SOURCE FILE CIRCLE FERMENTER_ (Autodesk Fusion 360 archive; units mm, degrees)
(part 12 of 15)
work_plane "Piano di lavoro1" AlongDistance -5
sketch "Schizzo2" plane through (-5, 0, 0) normal (1, 0, 0) x axis (0, 1, 0)
  line L1 (-88.4, 164.9) -> (-88.4, 163.1)
  curve K1 (-88.3168, 169.8415) -> (-88.4, 164.9)
  curve K2 (-81.9366, 174.4086) -> (-88.3168, 169.8415)
  curve K3 (-69.9527, 188.2187) -> (-74.509, 181.8379)
  curve K4 (-65, 188.3) -> (-69.9527, 188.2187)
  line L2 (-10.9836, 188.3) -> (-65, 188.3)
  line L3 (65, 188.3) -> (10.9836, 188.3)
  curve K5 (65, 188.3) -> (69.9527, 188.2187)
  curve K6 (69.9527, 188.2187) -> (74.509, 181.8379)
  curve K7 (81.9366, 174.4086) -> (88.3168, 169.8415)
  curve K8 (88.3168, 169.8415) -> (88.4, 164.9)
  line L4 (88.4, 163.1) -> (88.4, 164.9)
  line L5 (86.4, 157.1) -> (86.4, 163.1)
  line L6 (88.2, 157.1) -> (86.4, 157.1)
  line L7 (88.2, 159.9) -> (88.2, 157.1)
  line L8 (90, 159.9) -> (88.2, 159.9)
  line L9 (90, 164.9) -> (90, 159.9)
  curve K9 (90, 164.9) -> (65, 189.9)
  line L10 (-65, 189.9) -> (65, 189.9)
  curve K10 (-90, 164.9) -> (-65, 189.9)
  line L11 (-90, 159.9) -> (-90, 164.9)
  line L12 (-88.2, 159.9) -> (-90, 159.9)
  line L13 (-88.2, 157.1) -> (-88.2, 159.9)
  line L14 (-86.4, 157.1) -> (-88.2, 157.1)
  line L15 (-86.4, 163.1) -> (-86.4, 157.1)
  line L16 (86.4, 163.1) -> (88.4, 163.1)
  line L17 (-88.4, 163.1) -> (-86.4, 163.1)
  circle C1 centre (80.2735, 180.1735) radius 1.75
  circle C2 centre (0, 183.9) radius 1.75
  circle C3 centre (-80.2735, 180.1735) radius 1.75
  arc A1 centre (-80.2735, 180.1735) radius 6 clockwise from (-74.509, 181.8379) to (-81.9366, 174.4086)
  arc A2 centre (-10.9836, 183.3) radius 5 clockwise from (-10.9836, 188.3) to (-5.9911, 183.5727)
  arc A3 centre (0, 183.9) radius 6 clockwise from (5.9911, 183.5727) to (-5.9911, 183.5727)
  arc A4 centre (10.9836, 183.3) radius 5 clockwise from (5.9911, 183.5727) to (10.9836, 188.3)
  arc A5 centre (80.2735, 180.1735) radius 6 clockwise from (81.9366, 174.4086) to (74.509, 181.8379)
  circle C4 centre (80.2735, 180.1735) radius 3
  circle C5 centre (0, 183.9) radius 3
  circle C6 centre (-80.2735, 180.1735) radius 3
  concentric C1 C4
  concentric C2 C5
  concentric C3 C6
  dimension "d1698" diameter C4 = 6
  dimension "d1699" diameter C5 = 6
  dimension "d1700" diameter C6 = 6
extrude "Estrusione3" cut sketch "Schizzo2" profile of C1 C2 C3 C4 C5 C6 against normal blind 17.158
fillet "Raccordo1" radius 1
component_from_bodies "Corpo->Comp2"
mirror "Specchio1" mirrorStitchTolerance 0.1
sketch "Schizzo1" plane through (0, 0, 0) normal (1, 0, 0) x axis (0, 1, 0)
  line L1 (54, 115) -> (-54, 115)
  line L2 (54, 116.8) -> (54, 115)
  curve K1 (64.9968, 129.9) -> (54, 116.8)
  line L3 (65, 129.9) -> (64.9968, 129.9)
  curve K2 (90, 154.9) -> (65, 129.9)
  line L4 (90, 159.9) -> (90, 154.9)
  line L5 (88.4, 159.9) -> (90, 159.9)
  line L6 (88.4, 154.9) -> (88.4, 159.9)
  curve K3 (88.3168, 149.9585) -> (88.4, 154.9)
  curve K4 (88.3168, 149.9585) -> (81.9366, 145.3914)
  curve K5 (74.509, 137.9621) -> (69.9527, 131.5813)
  curve K6 (65, 131.5) -> (69.9527, 131.5813)
  line L7 (64.418, 131.5) -> (65, 131.5)
  curve K7 (64.418, 131.5) -> (62.9273, 130.1669)
  curve K8 (62.9273, 130.1669) -> (62.64, 129.4383)
  curve K9 (62.64, 129.4383) -> (52, 116.8)
  line L8 (52, 116.6) -> (52, 116.8)
  line L9 (-52, 116.6) -> (52, 116.6)
  line L10 (-52, 116.8) -> (-52, 116.6)
  curve K10 (-62.64, 129.4383) -> (-52, 116.8)
  curve K11 (-62.9273, 130.1669) -> (-62.64, 129.4383)
  curve K12 (-64.418, 131.5) -> (-62.9273, 130.1669)
  line L11 (-65, 131.5) -> (-64.418, 131.5)
  curve K13 (-65, 131.5) -> (-69.9527, 131.5813)
  curve K14 (-74.509, 137.9621) -> (-69.9527, 131.5813)
  curve K15 (-88.3168, 149.9585) -> (-81.9366, 145.3914)
  curve K16 (-88.3168, 149.9585) -> (-88.4, 154.9)
  line L12 (-88.4, 159.9) -> (-88.4, 154.9)
  line L13 (-90, 159.9) -> (-88.4, 159.9)
  line L14 (-90, 154.9) -> (-90, 159.9)
  curve K17 (-90, 154.9) -> (-65, 129.9)
  line L15 (-64.9968, 129.9) -> (-65, 129.9)
  curve K18 (-64.9968, 129.9) -> (-54, 116.8)
  line L16 (-54, 115) -> (-54, 116.8)
  circle C1 centre (80.2735, 139.6265) radius 2
  circle C2 centre (-80.2735, 139.6265) radius 2
  arc A1 centre (80.2735, 139.6265) radius 6 clockwise from (74.509, 137.9621) to (81.9366, 145.3914)
  arc A2 centre (-80.2735, 139.6265) radius 6 clockwise from (-81.9366, 145.3914) to (-74.509, 137.9621)
extrude "Estrusione1" add sketch "Schizzo1" profile of C1 C2 against normal blind 4
sketch "Schizzo2" plane through (0, 0, 0) normal (1, 0, 0) x axis (0, 1, 0)
  circle C1 centre (-80.2735, 139.6265) radius 1.75
  circle C2 centre (80.2735, 139.6265) radius 1.75
  circle C3 centre (-80.2735, 139.6265) radius 2
  circle C4 centre (80.2735, 139.6265) radius 2
  dimension "d1709" diameter C1 = 3.5
  dimension "d1710" diameter C2 = 3.5
extrude "Estrusione2" cut sketch "Schizzo2" profile of C1 C2 against normal blind 32.997
work_plane "Piano di lavoro1" AlongDistance -6
sketch "Schizzo3" plane through (-6, 0, 0) normal (1, 0, 0) x axis (0, 1, 0)
  circle C1 centre (-80.2735, 139.6265) radius 1.75
  circle C2 centre (80.2735, 139.6265) radius 1.75
  circle C3 centre (80.2735, 139.6265) radius 3
  circle C4 centre (-80.2735, 139.6265) radius 3
  concentric C2 C3
  concentric C1 C4
  dimension "d1714" diameter C3 = 6
  dimension "d1715" diameter C4 = 6
extrude "Estrusione3" cut sketch "Schizzo3" against normal blind 15
fillet "Raccordo2" radius 2
sketch "Schizzo1" plane through (-160, 0, 0) normal (-1, 0, 0) x axis (0, -1, 0)
  line L1 (-65, 189.9) -> (65, 189.9)
  curve K1 (-90, 164.9) -> (-65, 189.9)
  line L2 (-90, 159.9) -> (-90, 164.9)
  line L3 (-85.9, 159.9) -> (-90, 159.9)
  curve K2 (-83.203, 163.6818) -> (-81.8715, 165.8329)
  curve K3 (-81.897, 166.2391) -> (-81.8715, 165.8329)
  curve K4 (-81.897, 166.2391) -> (-65, 181.8)
  line L4 (-6.3246, 181.8) -> (-65, 181.8)
  curve K5 (-5.9329, 181.7743) -> (-6.3246, 181.8)
  curve K6 (-5.9329, 181.7743) -> (-3.7812, 183.1048)
  curve K7 (5.9329, 181.7743) -> (3.7812, 183.1048)
  curve K8 (5.9329, 181.7743) -> (6.3246, 181.8)
  line L5 (65, 181.8) -> (6.3246, 181.8)
  curve K9 (81.897, 166.2391) -> (65, 181.8)
  curve K10 (81.897, 166.2391) -> (81.8715, 165.8329)
  curve K11 (83.203, 163.6818) -> (81.8715, 165.8329)
  line L6 (90, 159.9) -> (85.9, 159.9)
  line L7 (90, 164.9) -> (90, 159.9)
  curve K12 (90, 164.9) -> (65, 189.9)
  curve K13 (-3.614, 139.7143) -> (-6.3246, 138)
  line L8 (-65, 138) -> (-6.3246, 138)
  curve K14 (-81.897, 153.5609) -> (-65, 138)
  curve K15 (-81.897, 153.5609) -> (-80.184, 156.2868)
  line L9 (-90, 159.9) -> (-85.9, 159.9)
  line L10 (-90, 154.9) -> (-90, 159.9)
  curve K16 (-90, 154.9) -> (-65, 129.9)
  line L11 (65, 129.9) -> (-65, 129.9)
  curve K17 (90, 154.9) -> (65, 129.9)
  line L12 (90, 159.9) -> (90, 154.9)
  line L13 (85.9, 159.9) -> (90, 159.9)
  curve K18 (81.897, 153.5609) -> (80.184, 156.2868)
  curve K19 (81.897, 153.5609) -> (65, 138)
  line L14 (6.3246, 138) -> (65, 138)
  curve K20 (3.614, 139.7143) -> (6.3246, 138)
  line L15 (-88, 154.9) -> (-88, 159.9)
  curve K21 (-88, 154.9) -> (-65, 131.9)
  line L16 (65, 131.9) -> (-65, 131.9)
  curve K22 (88, 154.9) -> (65, 131.9)
  line L17 (88, 159.9) -> (88, 154.9)
  line L18 (88, 164.9) -> (88, 159.9)
  curve K23 (88, 164.9) -> (65, 187.9)
  line L19 (-65, 187.9) -> (65, 187.9)
  curve K24 (-88, 164.9) -> (-65, 187.9)
  line L20 (-88, 159.9) -> (-88, 164.9)
  arc A1 centre (-81.9, 159.9) radius 4 clockwise from (-85.9, 159.9) to (-83.203, 163.6818)
  arc A2 centre (0, 181.8) radius 4 clockwise from (-3.7812, 183.1048) to (3.7812, 183.1048)
  arc A3 centre (81.9, 159.9) radius 4 clockwise from (83.203, 163.6818) to (85.9, 159.9)
  arc A4 centre (0, 138) radius 4 clockwise from (-3.614, 139.7143) to (3.614, 139.7143)
  arc A5 centre (-81.9, 159.9) radius 4 clockwise from (-85.9, 159.9) to (-80.184, 156.2868)
  arc A6 centre (81.9, 159.9) radius 4 clockwise from (80.184, 156.2868) to (85.9, 159.9)
  circle C1 centre (-81.9, 159.9) radius 1.75
  circle C2 centre (0, 138) radius 1.75
  circle C3 centre (81.9, 159.9) radius 1.75
  dimension "d1724" = -2
extrude "Estrusione1" new body sketch "Schizzo1" profile of L3 A1 K2 K3 K4 L4 K5 K6 A2 K7 K8 L5 K9 K10 K11 A3 L6 A4 K13 L8 K14 K15 A5 L9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 along normal blind 3
sketch "Schizzo9" plane through (160, 0, 0) normal (-1, 0, 0) x axis (0, -1, 0)
  line L1 (14.45, 176.75) -> (14.45, 143.05)
  line L2 (74.85, 177.75) -> (15.45, 177.75)
  line L3 (75.85, 143.05) -> (75.85, 176.75)
  line L4 (15.45, 142.05) -> (74.85, 142.05)
  line L5 (9.65, 140) -> (9.65, 179.8)
  line L6 (3.873, 138) -> (7.65, 138)
  line L7 (-65, 138) -> (-3.873, 138)
  curve K1 (-76.9033, 139.6916) -> (-65, 138)
  curve K2 (-79.0124, 141.3132) -> (-76.9033, 139.6916)
  curve K3 (-81.9, 154.9) -> (-79.0124, 141.3132)
  line L8 (-81.9, 156.027) -> (-81.9, 154.9)
  line L9 (-81.9, 164.9) -> (-81.9, 163.773)
  curve K4 (-79.0124, 178.4868) -> (-81.9, 164.9)
  curve K5 (-76.9033, 180.1084) -> (-79.0124, 178.4868)
  curve K6 (-65, 181.8) -> (-76.9033, 180.1084)
  line L10 (-3.873, 181.8) -> (-65, 181.8)
  line L11 (7.65, 181.8) -> (3.873, 181.8)
  curve K7 (74.4055, 134.6069) -> (65, 134)
  curve K8 (81.0094, 137.6898) -> (74.4055, 134.6069)
  curve K9 (85.9, 154.9) -> (81.0094, 137.6898)
  line L12 (85.9, 164.9) -> (85.9, 154.9)
  curve K10 (81.0094, 182.1102) -> (85.9, 164.9)
  curve K11 (74.4056, 185.1931) -> (81.0094, 182.1102)
  curve K12 (65, 185.8) -> (74.4056, 185.1931)
  line L13 (-65, 185.8) -> (65, 185.8)
  curve K13 (-78.818, 183.6203) -> (-65, 185.8)
  curve K14 (-81.9485, 181.2032) -> (-78.818, 183.6203)
  curve K15 (-85.9, 164.9) -> (-81.9485, 181.2032)
  line L14 (-85.9, 154.9) -> (-85.9, 164.9)
  curve K16 (-81.9485, 138.5968) -> (-85.9, 154.9)
  curve K17 (-78.818, 136.1797) -> (-81.9485, 138.5968)
  curve K18 (-65, 134) -> (-78.818, 136.1797)
  line L15 (65, 134) -> (-65, 134)
  line L16 (-35.35, 159.9) -> (9.65, 159.9)
  line L17 (9.65, 159.9) -> (-35.35, 159.9)
  line L18 (9.65, 165.9) -> (9.65, 159.9)
  line L19 (-35.35, 165.9) -> (9.65, 165.9)
  line L20 (-35.35, 159.9) -> (-35.35, 165.9)
  line L21 (-35.35, 153.9) -> (9.65, 153.9)
  line L22 (-35.35, 159.9) -> (-35.35, 153.9)
  arc A1 centre (15.45, 176.75) radius 1 clockwise from (14.45, 176.75) to (15.45, 177.75)
  arc A2 centre (74.85, 176.75) radius 1 clockwise from (74.85, 177.75) to (75.85, 176.75)
  arc A3 centre (74.85, 143.05) radius 1 clockwise from (75.85, 143.05) to (74.85, 142.05)
  arc A4 centre (15.45, 143.05) radius 1 clockwise from (15.45, 142.05) to (14.45, 143.05)
  arc A5 centre (7.65, 140) radius 2 clockwise from (9.65, 140) to (7.65, 138)
  arc A6 centre (3.873, 139) radius 1 clockwise from (3.873, 138) to (2.9047, 138.75)
  arc A7 centre (0, 138) radius 3 clockwise from (-2.9047, 138.75) to (2.9047, 138.75)
  arc A8 centre (-3.873, 139) radius 1 clockwise from (-2.9047, 138.75) to (-3.873, 138)
  arc A9 centre (-80.9, 156.027) radius 1 clockwise from (-81.9, 156.027) to (-81.15, 156.9953)
  arc A10 centre (-81.9, 159.9) radius 3 clockwise from (-81.15, 162.8047) to (-81.15, 156.9953)
  arc A11 centre (-80.9, 163.773) radius 1 clockwise from (-81.15, 162.8047) to (-81.9, 163.773)
  arc A12 centre (-3.873, 180.8) radius 1 clockwise from (-3.873, 181.8) to (-2.9047, 181.05)
  arc A13 centre (0, 181.8) radius 3 clockwise from (2.9047, 181.05) to (-2.9047, 181.05)
  arc A14 centre (3.873, 180.8) radius 1 clockwise from (2.9047, 181.05) to (3.873, 181.8)
  arc A15 centre (7.65, 179.8) radius 2 clockwise from (7.65, 181.8) to (9.65, 179.8)
  circle C1 centre (-81.9, 159.9) radius 1.75
  circle C2 centre (81.9, 159.9) radius 1.75
  circle C3 centre (0, 138) radius 1.75
  circle C4 centre (0, 181.8) radius 1.75
  point P66 (9.65, 159.9)
  point P69 (9.65, 165.9)
  point P67 (-35.35, 159.9)
  point P73 (-35.35, 159.9)
  point P71 (9.65, 153.9)
  point P70 (-35.35, 165.9)
  point P72 (-35.35, 153.9)
  midpoint L5 P66
  perpendicular L5 L16
  horizontal L17
  vertical L18
  horizontal L19
  vertical L20
  coincident L5 P69
  symmetric P67 L16 P73
  symmetric L16 P69 P71
  symmetric L16 P70 P72
  dimension "d1727" distance L5 P67 = 45
  dimension "d1728" distance P67 P70 = 6
extrude "Estrusione7" new body sketch "Schizzo9" profile of L5 L17 L18 L19 L20 L21 L22 to an object
combine "Combina4"
sketch "Schizzo10" plane through (170, 0, 0) normal (1, 0, 0) x axis (0, 1, 0)
  curve K1 (-71.9729, 151.8273) -> (-72, 154.9)
  line L1 (-72, 164.9) -> (-72, 154.9)
  curve K2 (-72, 164.9) -> (-71.9729, 167.9727)
  curve K3 (-71.9729, 167.9727) -> (-68.0604, 171.8773)
  curve K4 (-68.0604, 171.8773) -> (-65, 171.9)
  line L2 (-30, 171.9) -> (-65, 171.9)
  curve K5 (-30, 171.9) -> (-26.9396, 171.8773)
  curve K6 (-26.9396, 171.8773) -> (-23.0271, 167.9727)
  curve K7 (-23.0271, 167.9727) -> (-23, 164.9)
  line L3 (-23, 154.9) -> (-23, 164.9)
  curve K8 (-23, 154.9) -> (-23.0271, 151.8273)
  curve K9 (-23.0271, 151.8273) -> (-26.9396, 147.9227)
  curve K10 (-26.9396, 147.9227) -> (-30, 147.9)
  line L4 (-65, 147.9) -> (-30, 147.9)
  curve K11 (-65, 147.9) -> (-68.0604, 147.9227)
  curve K12 (-68.0604, 147.9227) -> (-71.9729, 151.8273)
  line L5 (-85.9, 154.9) -> (-85.9, 164.9)
  curve K13 (-65, 134) -> (-85.9, 154.9)
  line L6 (65, 134) -> (-65, 134)
  curve K14 (85.9, 154.9) -> (65, 134)
  line L7 (85.9, 164.9) -> (85.9, 154.9)
  curve K15 (85.9, 164.9) -> (65, 185.8)
  line L8 (-65, 185.8) -> (65, 185.8)
  curve K16 (-65, 185.8) -> (-85.9, 164.9)
  circle C1 centre (-5.2385, 159.9) radius 2.5
  circle C2 centre (9.7615, 159.9) radius 2.5
  circle C3 centre (24.7615, 159.9) radius 2.5
  circle C4 centre (60, 159.9) radius 3.5
  circle C5 centre (81.9, 159.9) radius 1.75
  circle C6 centre (0, 181.8) radius 1.75
  circle C7 centre (0, 138) radius 1.75
  circle C8 centre (-81.9, 159.9) radius 1.75
extrude "Estrusione1" cut sketch "Schizzo10" profile of C1 C2 C3 against normal blind 25.97
fillet "Raccordo3" radius 8 6
sketch "Schizzo8" plane through (170, 0, 0) normal (1, 0, 0) x axis (0, 1, 0)
  curve K1 (-71.9729, 151.8273) -> (-72, 154.9)
  line L1 (-72, 164.9) -> (-72, 154.9)
  curve K2 (-72, 164.9) -> (-71.9729, 167.9727)
  curve K3 (-71.9729, 167.9727) -> (-68.0604, 171.8773)
  curve K4 (-68.0604, 171.8773) -> (-65, 171.9)
  line L2 (-30, 171.9) -> (-65, 171.9)
  curve K5 (-30, 171.9) -> (-26.9396, 171.8773)
  curve K6 (-26.9396, 171.8773) -> (-23.0271, 167.9727)
  curve K7 (-23.0271, 167.9727) -> (-23, 164.9)
  line L3 (-23, 154.9) -> (-23, 164.9)
  curve K8 (-23, 154.9) -> (-23.0271, 151.8273)
  curve K9 (-23.0271, 151.8273) -> (-26.9396, 147.9227)
  curve K10 (-26.9396, 147.9227) -> (-30, 147.9)
  line L4 (-65, 147.9) -> (-30, 147.9)
  curve K11 (-65, 147.9) -> (-68.0604, 147.9227)
  curve K12 (-68.0604, 147.9227) -> (-71.9729, 151.8273)
  line L5 (-85.9, 154.9) -> (-85.9, 164.9)
  curve K13 (-65, 134) -> (-85.9, 154.9)
  line L6 (65, 134) -> (-65, 134)
  curve K14 (85.9, 154.9) -> (65, 134)
  line L7 (85.9, 164.9) -> (85.9, 154.9)
  curve K15 (85.9, 164.9) -> (65, 185.8)
  line L8 (-65, 185.8) -> (65, 185.8)
  curve K16 (-65, 185.8) -> (-85.9, 164.9)
  circle C1 centre (-5.2385, 159.9) radius 2.5
  circle C2 centre (9.7615, 159.9) radius 2.5
  circle C3 centre (24.7615, 159.9) radius 2.5
  circle C4 centre (60, 159.9) radius 3.5
  circle C5 centre (81.9, 159.9) radius 1.75
  circle C6 centre (0, 181.8) radius 1.75
  circle C7 centre (0, 138) radius 1.75
  circle C8 centre (-81.9, 159.9) radius 1.75
extrude "Estrusione5" add sketch "Schizzo8" profile of C1 C2 C3 against normal blind 3
component_from_bodies "Corpo->Comp1"
component_from_bodies "Corpo->Comp2"
component_from_bodies "Corpo->Comp1"
component_from_bodies "Corpo->Comp2"
component_from_bodies "Corpo->Comp1"
component_from_bodies "Corpo->Comp2"
sketch "Schizzo9" plane through (-160, 0, 0) normal (1, 0, 0) x axis (0, 1, 0)
  line L1 (-65, 187.9) -> (65, 187.9)
  curve K1 (-88, 164.9) -> (-65, 187.9)
  line L2 (-88, 154.9) -> (-88, 164.9)
  curve K2 (-88, 154.9) -> (-65, 131.9)
  line L3 (65, 131.9) -> (-65, 131.9)
  curve K3 (88, 154.9) -> (65, 131.9)
  line L4 (88, 164.9) -> (88, 154.9)
  curve K4 (88, 164.9) -> (65, 187.9)
  circle C1 centre (81.9, 159.9) radius 1.75
  circle C2 centre (-81.9, 159.9) radius 1.75
  circle C3 centre (0, 138) radius 1.75
sketch "Schizzo10" plane through (170, 0, 0) normal (1, 0, 0) x axis (0, 1, 0)
  curve K1 (-71.9729, 151.8273) -> (-72, 154.9)
  line L1 (-72, 164.9) -> (-72, 154.9)
  curve K2 (-72, 164.9) -> (-71.9729, 167.9727)
  curve K3 (-71.9729, 167.9727) -> (-68.0604, 171.8773)
  curve K4 (-68.0604, 171.8773) -> (-65, 171.9)
  line L2 (-30, 171.9) -> (-65, 171.9)
  curve K5 (-30, 171.9) -> (-26.9396, 171.8773)
  curve K6 (-26.9396, 171.8773) -> (-23.0271, 167.9727)
  curve K7 (-23.0271, 167.9727) -> (-23, 164.9)
  line L3 (-23, 154.9) -> (-23, 164.9)
  curve K8 (-23, 154.9) -> (-23.0271, 151.8273)
  curve K9 (-23.0271, 151.8273) -> (-26.9396, 147.9227)
  curve K10 (-26.9396, 147.9227) -> (-30, 147.9)
  line L4 (-65, 147.9) -> (-30, 147.9)
  curve K11 (-65, 147.9) -> (-68.0604, 147.9227)
  curve K12 (-68.0604, 147.9227) -> (-71.9729, 151.8273)
  line L5 (-85.9, 154.9) -> (-85.9, 164.9)
  curve K13 (-65, 134) -> (-85.9, 154.9)
  line L6 (65, 134) -> (-65, 134)
  curve K14 (85.9, 154.9) -> (65, 134)
  line L7 (85.9, 164.9) -> (85.9, 154.9)
  curve K15 (85.9, 164.9) -> (65, 185.8)
  line L8 (-65, 185.8) -> (65, 185.8)
  curve K16 (-65, 185.8) -> (-85.9, 164.9)
  circle C1 centre (60, 159.9) radius 3.5
  circle C2 centre (81.9, 159.9) radius 1.75
  circle C3 centre (0, 181.8) radius 1.75
  circle C4 centre (0, 138) radius 1.75
  circle C5 centre (-81.9, 159.9) radius 1.75
copy_paste "TagliaIncolla1"
sketch "Schizzo11" plane through (158, 0, 0) normal (1, 0, 0) x axis (0, 1, 0)
  line L1 (-86.7, -206.7) -> (-86.7, -127.1)
  line L2 (-82.7, -206.7) -> (-86.7, -206.7)
  curve K1 (-64.8, -224.6) -> (-82.7, -206.7)
  line L3 (-64.8, -228.6) -> (-64.8, -224.6)
  line L4 (64.8, -228.6) -> (-64.8, -228.6)
  line L5 (64.8, -224.6) -> (64.8, -228.6)
  curve K2 (82.7, -206.7) -> (64.8, -224.6)
  line L6 (86.7, -206.7) -> (82.7, -206.7)
  line L7 (86.7, -127.1) -> (86.7, -206.7)
  line L8 (82.7, -127.1) -> (86.7, -127.1)
  curve K3 (64.8, -109.2) -> (82.7, -127.1)
  line L9 (64.8, -105.2) -> (64.8, -109.2)
  line L10 (-64.8, -105.2) -> (64.8, -105.2)
  line L11 (-64.8, -109.2) -> (-64.8, -105.2)
  curve K4 (-82.7, -127.1) -> (-64.8, -109.2)
  line L12 (-86.7, -127.1) -> (-82.7, -127.1)
  circle C1 centre (-45, -110.3265) radius 1.75
  circle C2 centre (45, -110.3265) radius 1.75
  circle C3 centre (-81.5735, -166.9) radius 1.75
  circle C4 centre (81.5735, -166.9) radius 1.75
  circle C5 centre (45, -223.4735) radius 1.75
  circle C6 centre (-45, -223.4735) radius 1.75
sketch "Schizzo12" plane through (0, 0, -227.3) normal (0, 0, 1) x axis (-1, 0, 0)
  line L1 (-95, 64.5) -> (95, 64.5)
  curve K1 (-134.5, 25) -> (-95, 64.5)
  line L2 (-134.5, -25) -> (-134.5, 25)
  curve K2 (-134.5, -25) -> (-95, -64.5)
  line L3 (95, -64.5) -> (-95, -64.5)
  curve K3 (134.5, -25) -> (95, -64.5)
  line L4 (134.5, 25) -> (134.5, -25)
  curve K4 (134.5, 25) -> (95, 64.5)
  circle C1 centre (47.5, 60) radius 1.75
  circle C2 centre (130, 25) radius 1.75
  circle C3 centre (95, -60) radius 1.75
  circle C4 centre (130, -25) radius 1.75
  circle C5 centre (-47.5, -60) radius 1.75
  circle C6 centre (-130, -25) radius 1.75
  circle C7 centre (-130, 25) radius 1.75
  circle C8 centre (-47.5, 60) radius 1.75
sketch "Schizzo13" plane through (0, 85.4, 0) normal (0, -1, 0) x axis (1, 0, 0)
  curve K1 (95, -127.4) -> (134.5, -166.9)
  line L1 (-95, -127.4) -> (95, -127.4)
  curve K2 (-95, -127.4) -> (-134.5, -166.9)
  curve K3 (-134.5, -166.9) -> (-95, -206.4)
  line L2 (95, -206.4) -> (-95, -206.4)
  curve K4 (134.5, -166.9) -> (95, -206.4)
  circle C1 centre (-130, -166.9) radius 1.75
  circle C2 centre (130, -166.9) radius 1.75
  circle C3 centre (47.5, -131.9) radius 1.75
  circle C4 centre (-47.5, -131.9) radius 1.75
  circle C5 centre (47.5, -201.9) radius 1.75
  circle C6 centre (-47.5, -201.9) radius 1.75
sketch "Schizzo14" plane through (0, -75.4, 0) normal (0, -1, 0) x axis (1, 0, 0)
  line L1 (142, -159.4) -> (-142, -159.4)
  curve K1 (143, -158.4) -> (142, -159.4)
  line L2 (143, -144.4) -> (143, -158.4)
  curve K2 (142, -143.4) -> (143, -144.4)
  line L3 (-142, -143.4) -> (142, -143.4)
  curve K3 (-142, -143.4) -> (-143, -144.4)
  line L4 (-143, -158.4) -> (-143, -144.4)
  curve K4 (-143, -158.4) -> (-142, -159.4)
  circle C1 centre (-139, -147.4) radius 1.75
  circle C2 centre (-139, -155.4) radius 1.75
  circle C3 centre (139, -155.4) radius 1.75
  circle C4 centre (139, -147.4) radius 1.75
remove_instance "RimuoviIstanza1"
sketch "Schizzo15" plane through (-183, 0, 0) normal (-1, 0, 0) x axis (0, -1, 0)
  line L1 (39.4, -144) -> (-39.4, -144)
  line L2 (45.9, -183.3) -> (45.9, -150.5)
  line L3 (-39.4, -189.8) -> (39.4, -189.8)
  line L4 (-45.9, -150.5) -> (-45.9, -183.3)
  line L5 (-86.5355, -176.1047) -> (-79.4522, -169.0213)
  line L6 (-88, -206.9) -> (-88, -179.6402)
  curve K1 (-88, -206.9) -> (-65, -229.9)
  line L7 (65, -229.9) -> (-65, -229.9)
  curve K2 (88, -206.9) -> (65, -229.9)
  line L8 (88, -179.6402) -> (88, -206.9)
  line L9 (79.4522, -169.0213) -> (86.5355, -176.1047)
  line L10 (86.5355, -157.6954) -> (79.4522, -164.7787)
  line L11 (88, -126.9) -> (88, -154.1598)
  curve K3 (88, -126.9) -> (65, -103.9)
  line L12 (-65, -103.9) -> (65, -103.9)
  curve K4 (-88, -126.9) -> (-65, -103.9)
  line L13 (-88, -154.1598) -> (-88, -126.9)
  line L14 (-79.4522, -164.7787) -> (-86.5355, -157.6954)
  arc A1 centre (39.4, -150.5) radius 6.5 clockwise from (39.4, -144) to (45.9, -150.5)
  arc A2 centre (39.4, -183.3) radius 6.5 clockwise from (45.9, -183.3) to (39.4, -189.8)
  arc A3 centre (-39.4, -183.3) radius 6.5 clockwise from (-39.4, -189.8) to (-45.9, -183.3)
  arc A4 centre (-39.4, -150.5) radius 6.5 clockwise from (-45.9, -150.5) to (-39.4, -144)
  circle C1 centre (-25, -107.5) radius 1.75
  circle C2 centre (25, -107.5) radius 1.75
  arc A5 centre (-81.5735, -166.9) radius 3 clockwise from (-79.4522, -164.7787) to (-79.4522, -169.0213)
  arc A6 centre (-83, -179.6402) radius 5 clockwise from (-88, -179.6402) to (-86.5355, -176.1047)
  arc A7 centre (83, -179.6402) radius 5 clockwise from (86.5355, -176.1047) to (88, -179.6402)
  arc A8 centre (81.5735, -166.9) radius 3 clockwise from (79.4522, -169.0213) to (79.4522, -164.7787)
  arc A9 centre (83, -154.1598) radius 5 clockwise from (88, -154.1598) to (86.5355, -157.6954)
  arc A10 centre (-83, -154.1598) radius 5 clockwise from (-86.5355, -157.6954) to (-88, -154.1598)
  circle C3 centre (25, -226.3) radius 1.75
  circle C4 centre (-25, -226.3) radius 1.75
sketch "Schizzo16" plane through (-150.8, 0, 0) normal (1, 0, 0) x axis (0, 1, 0)
  line L1 (-10.25, -207.2618) -> (10.25, -207.2618)
  line L2 (-10.25, -192.7618) -> (-10.25, -207.2618)
  line L3 (10.25, -192.7618) -> (-10.25, -192.7618)
  line L4 (10.25, -207.2618) -> (10.25, -192.7618)
  line L5 (83.1107, -126.9) -> (83.1107, -164.9033)
  curve K1 (65, -108.7893) -> (83.1107, -126.9)
  line L6 (-65, -108.7893) -> (65, -108.7893)
  curve K2 (-83.1107, -126.9) -> (-65, -108.7893)
  line L7 (-83.1107, -164.9033) -> (-83.1107, -126.9)
  line L8 (-83.1107, -206.9) -> (-83.1107, -168.8967)
  curve K3 (-65, -225.0107) -> (-83.1107, -206.9)
  line L9 (65, -225.0107) -> (-65, -225.0107)
  curve K4 (83.1107, -206.9) -> (65, -225.0107)
  line L10 (83.1107, -168.8967) -> (83.1107, -206.9)
  circle C1 centre (12.35, -200.0107) radius 1.55
  circle C2 centre (-39, -182.9) radius 1.875
  circle C3 centre (39, -182.9) radius 1.725
  circle C4 centre (-39, -150.9) radius 1.875
  circle C5 centre (39, -150.9) radius 1.725
  circle C6 centre (-21, -166.9) radius 12.5
  circle C7 centre (23, -166.9) radius 19.5
  circle C8 centre (0, -222.1) radius 1.75
  circle C9 centre (44.1, -111.7) radius 1.75
  arc A1 centre (82.6107, -168.8967) radius 0.5 clockwise from (82.3802, -168.453) to (83.1107, -168.8967)
  arc A2 centre (81.5735, -166.9) radius 1.75 clockwise from (82.3802, -168.453) to (82.3802, -165.347)
  arc A3 centre (82.6107, -164.9033) radius 0.5 clockwise from (83.1107, -164.9033) to (82.3802, -165.347)
  arc A4 centre (-82.6107, -164.9033) radius 0.5 clockwise from (-82.3802, -165.347) to (-83.1107, -164.9033)
  arc A5 centre (-81.5735, -166.9) radius 1.75 clockwise from (-82.3802, -165.347) to (-82.3802, -168.453)
  arc A6 centre (-82.6107, -168.8967) radius 0.5 clockwise from (-83.1107, -168.8967) to (-82.3802, -168.453)
  circle C10 centre (44.1, -222.1) radius 1.75
  circle C11 centre (-44.1, -222.1) radius 1.75
  circle C12 centre (-44.1, -111.7) radius 1.75
  circle C13 centre (0, -111.7) radius 1.75
sketch "Schizzo17" plane through (158, 0, 0) normal (1, 0, 0) x axis (0, 1, 0)
  line L1 (86.7, 91.3) -> (86.7, -63.3)
  line L2 (82.7, 91.3) -> (86.7, 91.3)
  curve K1 (64.8, 109.2) -> (82.7, 91.3)
  line L3 (64.8, 113.2) -> (64.8, 109.2)
  line L4 (-64.8, 113.2) -> (64.8, 113.2)
  line L5 (-64.8, 109.2) -> (-64.8, 113.2)
  curve K2 (-82.7, 91.3) -> (-64.8, 109.2)
  line L6 (-86.7, 91.3) -> (-82.7, 91.3)
  line L7 (-86.7, -63.3) -> (-86.7, 91.3)
  line L8 (-82.7, -63.3) -> (-86.7, -63.3)
  curve K3 (-64.8, -81.2) -> (-82.7, -63.3)
  line L9 (-64.8, -85.2) -> (-64.8, -81.2)
  line L10 (64.8, -85.2) -> (-64.8, -85.2)
  line L11 (64.8, -81.2) -> (64.8, -85.2)
  curve K4 (82.7, -63.3) -> (64.8, -81.2)
  line L12 (86.7, -63.3) -> (82.7, -63.3)
  circle C1 centre (81.5735, 14) radius 1.75
  circle C2 centre (-81.5735, 14) radius 1.75
  circle C3 centre (-81.5735, 71.5) radius 1.75
  circle C4 centre (-45, 108.0735) radius 1.75
  circle C5 centre (45, 108.0735) radius 1.75
  circle C6 centre (81.5735, 71.5) radius 1.75
  circle C7 centre (0, 108.0735) radius 1.75
  circle C8 centre (0, -80.0735) radius 1.75
  circle C9 centre (81.5735, -43.5) radius 1.75
  circle C10 centre (45, -80.0735) radius 1.75
  circle C11 centre (-45, -80.0735) radius 1.75
  circle C12 centre (-81.5735, -43.5) radius 1.75
sketch "Schizzo18" plane through (0, 0, -83.9) normal (0, 0, 1) x axis (-1, 0, 0)
  line L1 (-90, -28.4) -> (-26.2258, -28.4)
  curve K1 (-98.4, -20) -> (-90, -28.4)
  line L2 (-98.4, 20) -> (-98.4, -20)
  curve K2 (-90, 28.4) -> (-98.4, 20)
  line L3 (-26.2258, 28.4) -> (-90, 28.4)
  line L4 (74.1572, 16.6179) -> (-14.0208, 27.6401)
  line L5 (89.206, 6.8768) -> (81.4524, 13.4232)
  line L6 (81.4524, -13.4232) -> (89.206, -6.8768)
  line L7 (-14.0208, -27.6401) -> (74.1572, -16.6179)
  line L8 (-95, 64.5) -> (95, 64.5)
  curve K3 (-134.5, 25) -> (-95, 64.5)
  line L9 (-134.5, -25) -> (-134.5, 25)
  curve K4 (-134.5, -25) -> (-95, -64.5)
  line L10 (95, -64.5) -> (-95, -64.5)
  curve K5 (134.5, -25) -> (95, -64.5)
  line L11 (134.5, 25) -> (134.5, -25)
  curve K6 (134.5, 25) -> (95, 64.5)
  arc A1 centre (-26.2258, 70) radius 98.4 clockwise from (-14.0208, -27.6401) to (-26.2258, -28.4)
  arc A2 centre (-26.2258, -70) radius 98.4 clockwise from (-26.2258, 28.4) to (-14.0208, 27.6401)
  arc A3 centre (72.4207, 2.726) radius 14 clockwise from (74.1572, 16.6179) to (81.4524, 13.4232)
  arc A4 centre (83.4, 0) radius 9 clockwise from (89.206, 6.8768) to (89.206, -6.8768)
  arc A5 centre (72.4207, -2.726) radius 14 clockwise from (81.4524, -13.4232) to (74.1572, -16.6179)
  circle C1 centre (88, 16) radius 1.75
  circle C2 centre (-101.9, -16) radius 1.75
  circle C3 centre (88, -16) radius 1.75
  circle C4 centre (-101.9, 16) radius 1.75
  circle C5 centre (130, 25) radius 1.75
  circle C6 centre (95, 60) radius 1.75
  circle C7 centre (32, 60) radius 1.75
  circle C8 centre (32, -60) radius 1.75
  circle C9 centre (95, -60) radius 1.75
  circle C10 centre (130, -25) radius 1.75
  circle C11 centre (-130, -25) radius 1.75
  circle C12 centre (-95, -60) radius 1.75
  circle C13 centre (-32, -60) radius 1.75
  circle C14 centre (-32, 60) radius 1.75
  circle C15 centre (-95, 60) radius 1.75
  circle C16 centre (-130, 25) radius 1.75
sketch "Schizzo19" plane through (0, 0, 111.9) normal (0, 0, -1) x axis (1, 0, 0)
  line L1 (95, -64.5) -> (-95, -64.5)
  curve K1 (95, -64.5) -> (134.5, -25)
  line L2 (134.5, 25) -> (134.5, -25)
  curve K2 (95, 64.5) -> (134.5, 25)
  line L3 (-95, 64.5) -> (95, 64.5)
  curve K3 (-95, 64.5) -> (-134.5, 25)
  line L4 (-134.5, -25) -> (-134.5, 25)
  curve K4 (-95, -64.5) -> (-134.5, -25)
  circle C1 centre (-130, 25) radius 1.75
  circle C2 centre (-95, 60) radius 1.75
  circle C3 centre (-32, 60) radius 1.75
  circle C4 centre (-32, -60) radius 1.75
  circle C5 centre (-95, -60) radius 1.75
  circle C6 centre (-130, -25) radius 1.75
  circle C7 centre (130, -25) radius 1.75
  circle C8 centre (95, -60) radius 1.75
  circle C9 centre (32, -60) radius 1.75
  circle C10 centre (32, 60) radius 1.75
  circle C11 centre (95, 60) radius 1.75
  circle C12 centre (130, 25) radius 1.75
sketch "Schizzo20" plane through (0, 85.4, 0) normal (0, -1, 0) x axis (1, 0, 0)
  line L1 (134.5, 51.5) -> (134.5, -23.5)
  curve K1 (95, 91) -> (134.5, 51.5)
  line L2 (-95, 91) -> (95, 91)
  curve K2 (-95, 91) -> (-134.5, 51.5)
  line L3 (-134.5, -23.5) -> (-134.5, 51.5)
  curve K3 (-134.5, -23.5) -> (-95, -63)
  line L4 (95, -63) -> (-95, -63)
  curve K4 (134.5, -23.5) -> (95, -63)
  circle C1 centre (-130, 51.5) radius 1.75
  circle C2 centre (-32, -58.5) radius 1.75
  circle C3 centre (-95, 86.5) radius 1.75
  circle C4 centre (-32, 86.5) radius 1.75
  circle C5 centre (-95, -58.5) radius 1.75
  circle C6 centre (-130, -23.5) radius 1.75
  circle C7 centre (130, -23.5) radius 1.75
  circle C8 centre (95, -58.5) radius 1.75
  circle C9 centre (32, 86.5) radius 1.75
  circle C10 centre (95, 86.5) radius 1.75
  circle C11 centre (32, -58.5) radius 1.75
  circle C12 centre (130, 51.5) radius 1.75
component_from_bodies "Corpo->Comp1"
component_from_bodies "Corpo->Comp1"
sketch "Schizzo21" plane through (-183, 0, 0) normal (-1, 0, 0) x axis (0, -1, 0)
  line L1 (65, -86.5) -> (-65, -86.5)
  curve K1 (88, -63.5) -> (65, -86.5)
  line L2 (88, -56.2402) -> (88, -63.5)
  line L3 (79.4522, -45.6213) -> (86.5355, -52.7047)
  line L4 (86.5355, -34.2953) -> (79.4522, -41.3787)
  line L5 (88, 58.7598) -> (88, -30.7598)
  line L6 (79.4522, 69.3787) -> (86.5355, 62.2953)
  line L7 (86.5355, 80.7047) -> (79.4522, 73.6213)
  line L8 (88, 91.5) -> (88, 84.2402)
  curve K2 (65, 114.5) -> (88, 91.5)
  line L9 (-65, 114.5) -> (65, 114.5)
  curve K3 (-65, 114.5) -> (-88, 91.5)
  line L10 (-88, 84.2402) -> (-88, 91.5)
  line L11 (-79.4522, 73.6213) -> (-86.5355, 80.7047)
  line L12 (-86.5355, 62.2953) -> (-79.4522, 69.3787)
  line L13 (-88, -30.7598) -> (-88, 58.7598)
  line L14 (-79.4522, -41.3787) -> (-86.5355, -34.2953)
  line L15 (-86.5355, -52.7047) -> (-79.4522, -45.6213)
  line L16 (-88, -63.5) -> (-88, -56.2402)
  curve K4 (-88, -63.5) -> (-65, -86.5)
  line L17 (-36.4, -31.9) -> (36.4, -31.9)
  line L18 (-42.9, 53.4) -> (-42.9, -25.4)
  line L19 (36.4, 59.9) -> (-36.4, 59.9)
  line L20 (42.9, -25.4) -> (42.9, 53.4)
  circle C1 centre (55.4256, 46) radius 1.75
  circle C2 centre (-55.4256, 46) radius 1.75
  circle C3 centre (0, -50) radius 1.75
  arc A1 centre (83, -56.2402) radius 5 clockwise from (86.5355, -52.7047) to (88, -56.2402)
  arc A2 centre (81.5735, -43.5) radius 3 clockwise from (79.4522, -45.6213) to (79.4522, -41.3787)
  arc A3 centre (83, -30.7598) radius 5 clockwise from (88, -30.7598) to (86.5355, -34.2953)
  arc A4 centre (83, 58.7598) radius 5 clockwise from (86.5355, 62.2953) to (88, 58.7598)
  arc A5 centre (81.5735, 71.5) radius 3 clockwise from (79.4522, 69.3787) to (79.4522, 73.6213)
  arc A6 centre (83, 84.2402) radius 5 clockwise from (88, 84.2402) to (86.5355, 80.7047)
  arc A7 centre (-83, 84.2402) radius 5 clockwise from (-86.5355, 80.7047) to (-88, 84.2402)
  arc A8 centre (-81.5735, 71.5) radius 3 clockwise from (-79.4522, 73.6213) to (-79.4522, 69.3787)
  arc A9 centre (-83, 58.7598) radius 5 clockwise from (-88, 58.7598) to (-86.5355, 62.2953)
  arc A10 centre (-83, -30.7598) radius 5 clockwise from (-86.5355, -34.2953) to (-88, -30.7598)
  arc A11 centre (-81.5735, -43.5) radius 3 clockwise from (-79.4522, -41.3787) to (-79.4522, -45.6213)
  arc A12 centre (-83, -56.2402) radius 5 clockwise from (-88, -56.2402) to (-86.5355, -52.7047)
  circle C4 centre (-25, 110.9) radius 1.75
  circle C5 centre (-84.4, -11) radius 1.75
  circle C6 centre (-25, -82.9) radius 1.75
  circle C7 centre (-84.4, 39) radius 1.75
  circle C8 centre (84.4, 39) radius 1.75
  circle C9 centre (25, -82.9) radius 1.75
  circle C10 centre (84.4, -11) radius 1.75
  circle C11 centre (25, 110.9) radius 1.75
  arc A13 centre (-36.4, -25.4) radius 6.5 clockwise from (-36.4, -31.9) to (-42.9, -25.4)
  arc A14 centre (-36.4, 53.4) radius 6.5 clockwise from (-42.9, 53.4) to (-36.4, 59.9)
  arc A15 centre (36.4, 53.4) radius 6.5 clockwise from (36.4, 59.9) to (42.9, 53.4)
  arc A16 centre (36.4, -25.4) radius 6.5 clockwise from (42.9, -25.4) to (36.4, -31.9)
sketch "Schizzo22" plane through (-153.8, 0, 0) normal (-1, 0, 0) x axis (0, -1, 0)
  line L1 (-10.25, -63.8607) -> (10.25, -63.8607)
  line L2 (-10.25, -49.3607) -> (-10.25, -63.8607)
  line L3 (10.25, -49.3607) -> (-10.25, -49.3607)
  line L4 (10.25, -63.8607) -> (10.25, -49.3607)
  line L5 (20, 10.5) -> (-20, 10.5)
  line L6 (-20, -28.5) -> (20, -28.5)
  line L7 (-20, 22.5) -> (20, 22.5)
  line L8 (20, 47.5) -> (-20, 47.5)
  line L9 (-83.1107, -63.5) -> (-83.1107, -45.4967)
  curve K1 (-65, -81.6107) -> (-83.1107, -63.5)
  line L10 (65, -81.6107) -> (-65, -81.6107)
  curve K2 (83.1107, -63.5) -> (65, -81.6107)
  line L11 (83.1107, -45.4967) -> (83.1107, -63.5)
  line L12 (83.1107, 69.5033) -> (83.1107, -41.5033)
  line L13 (83.1107, 91.5) -> (83.1107, 73.4967)
  curve K3 (65, 109.6107) -> (83.1107, 91.5)
  line L14 (-65, 109.6107) -> (65, 109.6107)
  curve K4 (-83.1107, 91.5) -> (-65, 109.6107)
  line L15 (-83.1107, 73.4967) -> (-83.1107, 91.5)
  line L16 (-83.1107, -41.5033) -> (-83.1107, 69.5033)
  circle C1 centre (-12.35, -56.6107) radius 1.75
  circle C2 centre (-36, 53) radius 1.875
  arc A1 centre (-20, -9) radius 19.5 clockwise from (-20, -28.5) to (-20, 10.5)
  arc A2 centre (20, -9) radius 19.5 clockwise from (20, 10.5) to (20, -28.5)
  circle C3 centre (-36, -25) radius 1.725
  circle C4 centre (36, 53) radius 1.875
  arc A3 centre (-20, 35) radius 12.5 clockwise from (-20, 22.5) to (-20, 47.5)
  arc A4 centre (20, 35) radius 12.5 clockwise from (20, 47.5) to (20, 22.5)
  circle C5 centre (36, -25) radius 1.725
  circle C6 centre (44.1, -78.7) radius 1.75
  circle C7 centre (-44.1, -78.7) radius 1.75
  circle C8 centre (0, -78.7) radius 1.75
  circle C9 centre (44.1, 106.7) radius 1.75
  circle C10 centre (80.2, 14) radius 1.75
  circle C11 centre (-44.1, 106.7) radius 1.75
  circle C12 centre (0, 106.7) radius 1.75
  circle C13 centre (-80.2, 14) radius 1.75
  arc A5 centre (-82.6107, -41.5033) radius 0.5 clockwise from (-82.3802, -41.947) to (-83.1107, -41.5033)
  arc A6 centre (-81.5735, -43.5) radius 1.75 clockwise from (-82.3802, -41.947) to (-82.3802, -45.053)
  arc A7 centre (-82.6107, -45.4967) radius 0.5 clockwise from (-83.1107, -45.4967) to (-82.3802, -45.053)
  arc A8 centre (82.6107, -45.4967) radius 0.5 clockwise from (82.3802, -45.053) to (83.1107, -45.4967)
  arc A9 centre (81.5735, -43.5) radius 1.75 clockwise from (82.3802, -45.053) to (82.3802, -41.947)
  arc A10 centre (82.6107, -41.5033) radius 0.5 clockwise from (83.1107, -41.5033) to (82.3802, -41.947)
  arc A11 centre (82.6107, 69.5033) radius 0.5 clockwise from (82.3802, 69.947) to (83.1107, 69.5033)
  arc A12 centre (81.5735, 71.5) radius 1.75 clockwise from (82.3802, 69.947) to (82.3802, 73.053)
  arc A13 centre (82.6107, 73.4967) radius 0.5 clockwise from (83.1107, 73.4967) to (82.3802, 73.053)
  arc A14 centre (-82.6107, 73.4967) radius 0.5 clockwise from (-82.3802, 73.053) to (-83.1107, 73.4967)
  arc A15 centre (-81.5735, 71.5) radius 1.75 clockwise from (-82.3802, 73.053) to (-82.3802, 69.947)
  arc A16 centre (-82.6107, 69.5033) radius 0.5 clockwise from (-83.1107, 69.5033) to (-82.3802, 69.947)
remove_instance "RimuoviIstanza6"
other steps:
base_feature "Lavorazione di base1"
base_feature "Lavorazione di base1"
base_feature "Lavorazione di base1"
base_feature "Lavorazione di base1"
base_feature "Lavorazione di base1"
base_feature "Lavorazione di base1" bodies "BOTTOM SHELL FRONT"
base_feature "Lavorazione di base1"
base_feature "Lavorazione di base1" bodies "PROFILO BASE"
derived_base_feature "Lavorazione di base derivata1"
derived_base_feature "Lavorazione di base derivata1"
derived_base_feature "Lavorazione di base derivata1"
derived_base_feature "Lavorazione di base derivata1" bodies "binario"
derived_base_feature "Lavorazione di base derivata1"
derived_base_feature "Lavorazione di base derivata1"
base_feature "Lavorazione di base1"
base_feature "Lavorazione di base1" bodies "PROFILO BASE"
base_feature "Lavorazione di base1"
derived_base_feature "Lavorazione di base derivata1"
derived_base_feature "Lavorazione di base derivata1"
derived_base_feature "Lavorazione di base derivata1"
derived_base_feature "Lavorazione di base derivata1" bodies "binario"
derived_base_feature "Lavorazione di base derivata1"
derived_base_feature "Lavorazione di base derivata1"
base_feature "Lavorazione di base1"
base_feature "Lavorazione di base1" bodies "STAFFA", "binario"
base_feature "Lavorazione di base1"
base_feature "Lavorazione di base1"
derived_base_feature "Lavorazione di base derivata1" bodies "PROFILO BASE"
derived_base_feature "Lavorazione di base derivata1" bodies "PROFILO BASE"
derived_base_feature "Lavorazione di base derivata1" bodies "PROFILO BASE"
base_feature "Lavorazione di base1"
base_feature "Lavorazione di base1"
base_feature "Lavorazione di base1" bodies "ACRILICO SPORTELLO"
base_feature "Lavorazione di base1" bodies "STAFFA", "binario"
base_feature "Lavorazione di base1"
base_feature "Lavorazione di base1"
extrude "Estrusione1" cut sketch "Schizzo1" profile of C1 C2 C7 C8 L1 L3 L6 L7 against normal blind 3
base_feature "Lavorazione di base1"
base_feature "Lavorazione di base1" bodies "GUARNIZIONE"
base_feature "Lavorazione di base1" bodies "GUARNIZIONE (1)"
base_feature "Lavorazione di base1"
base_feature "Lavorazione di base1" bodies "PROFILO BASE PORTA"
base_feature "Lavorazione di base1" bodies "GUARNIZIONE"
base_feature "Lavorazione di base1" bodies "GUARNIZIONE (1)"
base_feature "Lavorazione di base1"
base_feature "Lavorazione di base1"
hole "Foratura1" HoleDepth 100 HoleDiameter 3.5 TipAngle 118 CSDiameter 6.7 CSAngle 90
mirror "Specchio1" mirrorStitchTolerance 0.1
mirror "Specchio2" mirrorStitchTolerance 0.1
base_feature "Lavorazione di base1"
base_feature "Lavorazione di base1"
base_feature "Lavorazione di base1"
extrude "Estrusione3" cut sketch "Schizzo3" profile of C5 C6 C7 C8 against normal blind 51.149
base_feature "Lavorazione di base1" bodies "ACRILICO SPORTELLO"
base_feature "Lavorazione di base1"
base_feature "Lavorazione di base1"
base_feature "Lavorazione di base1" bodies "PROFILO BASE PORTA"
hole "Foratura1" HoleDepth 12.597 HoleDiameter 3.5 TipAngle 180
base_feature "Lavorazione di base1"
hole "Foratura1" HoleDepth 100 named "d974_1" HoleDiameter 3.5 named "d975_1" TipAngle 118 named "d976_1" CSDiameter 6.7 named "d977_1" CSAngle 90 named "d978_1"
mirror "Specchio1" mirrorStitchTolerance 0.1 named "d987_1"
base_feature "Lavorazione di base1"
hole "Foratura1" HoleDepth 4.8 HoleDiameter 3.5 TipAngle 180
mirror "Specchio2" mirrorStitchTolerance 0.1 named "d991_1"
base_feature "Lavorazione di base1"
base_feature "Lavorazione di base1"
base_feature "Lavorazione di base1" bodies "PROFILO BASE"
base_feature "Lavorazione di base1"
base_feature "Lavorazione di base1"
extrude "Estrusione3" cut sketch "Schizzo3" profile of C5 C6 C7 C8 against normal blind 51.149 named "d964_1"
hole "Foratura1" HoleDepth 12.597 named "d1079_1" HoleDiameter 3.5 named "d1080_1" TipAngle 180 named "d1081_1"
base_feature "Lavorazione di base1"
base_feature "Lavorazione di base1"
base_feature "Lavorazione di base1" bodies "PROFILO BASE"
base_feature "Lavorazione di base1" bodies "PROFILO BASE PORTA"
base_feature "Lavorazione di base1" bodies "PROFILO BASE PORTA"
base_feature "Lavorazione di base1"
base_feature "Lavorazione di base1" bodies "PROFILO BASE"
create_component "CreaComponente1"
create_component "CreaComponente2"
create_component "CreaComponente3"
create_component "CreaComponente1"
remove_body "RimuoviCorpo2"
create_component "CreaComponente2"
remove_body "RimuoviCorpo3"
create_component "CreaComponente4"
create_component "CreaComponente1"
create_component "CreaComponente2"
create_component "CreaComponente3"
joint_origin "OrigineGiunto5"
joint_origin "OrigineGiunto6"
joint_origin "OrigineGiunto7"
joint_origin "OrigineGiunto8"
joint_origin "OrigineGiunto9"
joint_origin "OrigineGiunto10"
joint_origin "OrigineGiunto11"
joint_origin "OrigineGiunto12"
joint_origin "OrigineGiunto13"
joint_origin "OrigineGiunto14"
joint_origin "OrigineGiunto15"
joint_origin "OrigineGiunto16"
joint_origin "OrigineGiunto17"
joint_origin "OrigineGiunto18"
joint_origin "OrigineGiunto19"
joint_origin "OrigineGiunto20"
create_component "CreaComponente1"
remove_body "RimuoviCorpo1"
create_component "CreaComponente2"
remove_body "RimuoviCorpo2"
create_component "CreaComponente3"
remove_body "RimuoviCorpo3"
joint_origin "OrigineGiunto1"
joint_origin "OrigineGiunto1"
joint_origin "OrigineGiunto2"
joint_origin "OrigineGiunto1"
create_component "CreaComponente1"
create_component "CreaComponente3"
create_component "CreaComponente4"
remove_body "RimuoviCorpo5"
create_component "CreaComponente5"
remove_body "RimuoviCorpo6"
create_component "CreaComponente1"
remove_body "RimuoviCorpo1"
joint_origin "OrigineGiunto1"
joint_origin "OrigineGiunto2"
create_component "CreaComponente6"
create_component "CreaComponente1"
remove_body "RimuoviCorpo1"
joint_origin "OrigineGiunto1"
joint_origin "OrigineGiunto2"
create_component "CreaComponente7"
joint_origin "OrigineGiunto1"
create_component "CreaComponente8"
create_component "CreaComponente1"
remove_body "RimuoviCorpo1"
create_component "CreaComponente2"
remove_body "RimuoviCorpo2"
create_component "CreaComponente9"
create_component "CreaComponente1"
remove_body "RimuoviCorpo1"
create_component "CreaComponente2"
remove_body "RimuoviCorpo2"
joint_origin "OrigineGiunto1"
joint_origin "OrigineGiunto3"
joint_origin "OrigineGiunto4"
joint_origin "OrigineGiunto5"
joint_origin "OrigineGiunto6"
joint_origin "OrigineGiunto7"
create_component "CreaComponente2"
remove_body "RimuoviCorpo1"
create_component "CreaComponente3"
create_component "CreaComponente4"
create_component "CreaComponente5"
create_component "CreaComponente6"
create_component "CreaComponente7"
create_component "CreaComponente8"
create_component "CreaComponente10"
create_component "CreaComponente1"
remove_body "RimuoviCorpo1"
create_component "CreaComponente2"
remove_body "RimuoviCorpo2"
create_component "CreaComponente11"
create_component "CreaComponente12"
joint_origin "OrigineGiunto3"
joint_origin "OrigineGiunto3"
joint_origin "OrigineGiunto4"
create_component "CreaComponente1"
remove_body "RimuoviCorpo1"
create_component "CreaComponente2"
remove_body "RimuoviCorpo2"
joint_origin "OrigineGiunto2"
create_component "CreaComponente3"
remove_body "RimuoviCorpo3"
create_component "CreaComponente4"
joint_origin "OrigineGiunto4"
create_component "CreaComponente1"
create_component "CreaComponente5"
create_component "CreaComponente3"
joint_origin "OrigineGiunto3"
joint_origin "OrigineGiunto4"
remove_instance "RimuoviIstanza5"
create_component "CreaComponente1"
remove_body "RimuoviCorpo2"
create_component "CreaComponente2"
remove_body "RimuoviCorpo3"
joint_origin "OrigineGiunto5"
joint_origin "OrigineGiunto6"
joint_origin "OrigineGiunto7"
joint_origin "OrigineGiunto8"
joint_origin "OrigineGiunto9"
joint_origin "OrigineGiunto10"
joint_origin "OrigineGiunto11"
joint_origin "OrigineGiunto12"
joint_origin "OrigineGiunto13"
joint_origin "OrigineGiunto14"
joint_origin "OrigineGiunto15"
joint_origin "OrigineGiunto16"
joint_origin "OrigineGiunto17"
joint_origin "OrigineGiunto18"
joint_origin "OrigineGiunto19"
joint_origin "OrigineGiunto20"
create_component "CreaComponente1"
remove_body "RimuoviCorpo1"
create_component "CreaComponente2"
remove_body "RimuoviCorpo2"
create_component "CreaComponente3"
remove_body "RimuoviCorpo3"
joint_origin "OrigineGiunto1"
joint_origin "OrigineGiunto1"
joint_origin "OrigineGiunto2"
joint_origin "OrigineGiunto1"
create_component "CreaComponente1"
create_component "CreaComponente3"
create_component "CreaComponente4"
remove_body "RimuoviCorpo5"
create_component "CreaComponente5"
remove_body "RimuoviCorpo6"
create_component "CreaComponente1"
remove_body "RimuoviCorpo1"
joint_origin "OrigineGiunto1"
joint_origin "OrigineGiunto2"
create_component "CreaComponente6"
create_component "CreaComponente1"
remove_body "RimuoviCorpo1"
joint_origin "OrigineGiunto1"
joint_origin "OrigineGiunto2"
create_component "CreaComponente7"
create_component "CreaComponente8"
create_component "CreaComponente1"
remove_body "RimuoviCorpo1"
create_component "CreaComponente2"
remove_body "RimuoviCorpo2"
create_component "CreaComponente9"
create_component "CreaComponente1"
remove_body "RimuoviCorpo1"
create_component "CreaComponente2"
remove_body "RimuoviCorpo2"
joint_origin "OrigineGiunto1"
joint_origin "OrigineGiunto3"
create_component "CreaComponente2"
remove_body "RimuoviCorpo1"
create_component "CreaComponente3"
create_component "CreaComponente4"
create_component "CreaComponente5"
create_component "CreaComponente6"
create_component "CreaComponente7"
create_component "CreaComponente8"
create_component "CreaComponente10"
create_component "CreaComponente1"
remove_body "RimuoviCorpo1"
create_component "CreaComponente2"
remove_body "RimuoviCorpo2"
create_component "CreaComponente11"
create_component "CreaComponente12"
joint_origin "OrigineGiunto3"
joint_origin "OrigineGiunto3"
joint_origin "OrigineGiunto4"
create_component "CreaComponente1"
remove_body "RimuoviCorpo1"
create_component "CreaComponente2"
remove_body "RimuoviCorpo2"
create_component "CreaComponente3"
remove_body "RimuoviCorpo3"
create_component "CreaComponente4"
joint_origin "OrigineGiunto4"
create_component "CreaComponente1"
create_component "CreaComponente3"
joint_origin "OrigineGiunto3"
joint_origin "OrigineGiunto4"
create_component "CreaComponente6"
joint_origin "OrigineGiunto4"
joint_origin "OrigineGiunto5"
joint_origin "OrigineGiunto3"
joint_origin "OrigineGiunto6"
create_component "CreaComponente14"
joint_origin "OrigineGiunto7"
joint_origin "OrigineGiunto7"
joint_origin "OrigineGiunto5" sketch "Schizzo5"
create_component "CreaComponente7"
create_component "CreaComponente1"
create_component "CreaComponente2"
remove_body "RimuoviCorpo2"
create_component "CreaComponente1"
remove_body "RimuoviCorpo1"
remove_instance "RimuoviIstanza3"
joint_origin "OrigineGiunto1"
create_component "CreaComponente3"
joint_origin "OrigineGiunto2"
remove_body "RimuoviCorpo3"
remove_body "RimuoviCorpo4"
remove_body "RimuoviCorpo2"
remove_body "RimuoviCorpo3"
create_component "CreaComponente4"
remove_body "RimuoviCorpo1"
create_component "CreaComponente1"
remove_body "RimuoviCorpo12"
create_component "CreaComponente2"
remove_body "RimuoviCorpo13"
create_component "CreaComponente3"
remove_body "RimuoviCorpo5"
create_component "CreaComponente1"
remove_body "RimuoviCorpo1"
create_component "CreaComponente2"
remove_body "RimuoviCorpo4"
create_component "CreaComponente1"
remove_body "RimuoviCorpo1"
create_component "CreaComponente2"
remove_body "RimuoviCorpo2"
create_component "CreaComponente1"
remove_body "RimuoviCorpo1"
create_component "CreaComponente2"
remove_body "RimuoviCorpo2"
remove_instance "RimuoviIstanza1"
create_component "CreaComponente1"
remove_body "RimuoviCorpo1"
create_component "CreaComponente2"
remove_body "RimuoviCorpo1"
named bodies: "PROFILO BASE", "TEST ACRILICO", "TEST ACRILICO 2", "GUARNIZIONE", "GUARNIZIONE (1)", "TEST ACRILICO DAVANTI", "PROFILO BASE PORTA", "ACRILICO SPORTELLO", "STAFFA", "binario", "PROFILO BASE (1)", "PROFILO BASE (1) (1)", "PROFILO BASE (1) (1) (1)", "PROFILO BASE (1) (1) (2)", "PROFILO BASE (1) (1) (3)", "PROFILO BASE PORTA (1)", "PROFILO BASE PORTA (2)", "ACRILICO SPORTELLO (1)", "ACRILICO SPORTELLO (2)", "BOTTOM SHELL FRONT"

design "Vite a broccia con testa incassata ed esagono incassato ANSI B18.3.1M - M3x0.5 x 8 Designazione acciaio 2 Radente"
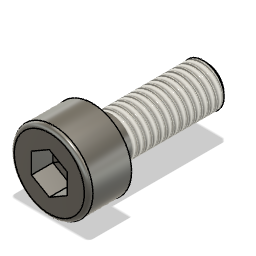
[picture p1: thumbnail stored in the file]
description: Part Number
part number: arrangementsContainer
parameter "adsk_nomlen" = 8
parameter "adsk_headh" = 3
parameter "adsk_headdia" = 5.5
parameter "adsk_nomdia" = 3
parameter "adsk_waflat" = 2.5
parameter "adsk_keyend" = 1.5
parameter "adsk_thrlen" = 6.6933
parameter "adsk_startlen" = 0.3067
parameter "adsk_endpointdia" = 2.3866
